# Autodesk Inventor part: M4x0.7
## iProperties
Created: 2009-02
Part Number: M4x0.7
Material: 강, 연강
Description: 6각머리 태핑 나사
Document SubType Name: Modeling
Standard: KS B 1003
Standards Organization: KS
Language: ko-KR
Size Designation: M 4 x 12
Categories: <MemberInstance><Categories><Category DisplayName="조임쇠" InternalName="e4da775c-781d-43d5-af7c-5136215cf5a6" Mnemonic="FSTN"><Category DisplayName="볼트" InternalN
Density: 1 g/cm^3
Checked By: KYOUNG IL JANG
Vendor: CBT Solutions
Designer: KYOUNG IL JANG
Manager: KYOUNG IL JANG
Company: 한국ATC센터
IsCustomPart: 0
Author: KYOUNG IL JANG
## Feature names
1. Fillet2
